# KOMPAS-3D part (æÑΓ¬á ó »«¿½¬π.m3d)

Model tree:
1. Эскиз:1
2. Операция выдавливания:1
     Расстояние 1 = 2.5
3. Эскиз:2
4. Вырезать элемент выдавливания:1
     Расстояние 1 = 2.5
5. Массив по сетке:1  (with: Вырезать элемент выдавливания:1)  (477 pattern instances)
     Шаг 1 = 12; Угол раствора = -90; Номер 1 = 1; Номер 2 = 1
6. Эскиз:3
7. Операция выдавливания:2
     Расстояние 1 = 8; Расстояние 2 = 5
8. Эскиз:4
9. Вырезать элемент выдавливания:2
     Расстояние 2 = 110; Расстояние 1 = 50

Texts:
  Сетка в поилку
